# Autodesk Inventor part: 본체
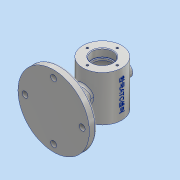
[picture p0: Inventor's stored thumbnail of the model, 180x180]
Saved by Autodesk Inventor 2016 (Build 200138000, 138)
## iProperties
Created: 2018-12
Part Number: 본체
Material: 알루미늄 6061
Document SubType Name: Modeling
Designer: 3sil_cad0123
Density: 2.7 g/cm^3
Appearance: 알루미늄 - 평지
Mass: 685.1 g
Surface Area: 555.675 cm^2
Volume: 253.741 cm^3
Author: 3sil_cad0123
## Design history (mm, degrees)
sketch "스케치2"
  geometry: C1 r 30 at (0, 0); C2 r 14 at (0, 0); C3 r 25 at (0, 0); 1 further point
  constraints: 3 centre point, 3 coincident
  dimensions: "d3" = 60 diameter of C1; "d4" = 28 diameter of C2; "d5" = 50 diameter of C3
extrude "돌출1" new body sketch "스케치2" stored distance "d6" = 70; taper "d7" = 0 deg
extrude "돌출2" cut sketch "스케치2" stored distance "d8" = 70; taper "d9" = 0 deg
extrude "돌출3" cut sketch "스케치2" stored distance "d10" = 40; taper "d11" = 0 deg
sketch "스케치3" dims "d13" = 46
  geometry: L1 (0, 0)-(0, 23); C1 r 14 at (0, 0) reference; C2 r 30 at (0, 0) reference; C3 r 16 at (0, 0); C4 r 1.692 at (0, 23)
  constraints: 3 coincident, 2 centre point, 2 end point, 1 vertical, 1 vertical alignment, 2 other
  dimensions: "d12" = 32 diameter of C3
extrude "돌출4" cut sketch "스케치3" distance "d14" = 12; taper "d15" = 0 deg
sketch "스케치4" dims "d16" = 46
  geometry: L1 (0, 23)-(0, 26.218); C1 r 30 at (0, 0) reference; 1 further point
  constraints: 2 end point, 1 coincident, 1 vertical, 1 vertical alignment, 2 other
hole "구멍1" sketch "스케치4" at (0, 23) diameter "d17" = 3.242; stored, may be unused: countersink angle "d21" = 90 deg, drill point angle "d23" = 118 deg; dims "d18" = 8, "d19" = 4, "d20" = 2, "d22" = 10
node "작업 평면1"
sketch "스케치5"
  geometry: L1 (0, -75)-(55, -75); L2 (55, -75)-(55, -64); L3 (0, -58.127)-(0, -75); L4 (0, -75)-(12, -75); L5 (12, -52.478)-(12, -26.195); L6 (12, -26.195)-(0, -26.195); L7 (0, -26.195)-(0, -75); L8 (55, -64)-(12, -52.478); L9 (0, 27.709)-(10, 27.709); L10 (10, 27.709)-(10, 37); L11 (10, 37)-(0, 37); L12 (0, 37)-(0, 27.709); 1 further point
  constraints: 24 end point, 5 parallel, 3 horizontal, 3 perpendicular
  dimensions: "d27" = 55 distance of L1.start L1.end; "d29" = 75 deg angle of L2 L8; "d30" = 12 distance between parallel lines of L5 L7; "d31" = 75 distance from line of point (0, 0) L1; "d32" = 11 distance of L1.end L2.end; "d33" = 10 distance of L10.end L11.end; "d34" = 112 distance between parallel lines of L11 L1
revolve "회전1" stored, may be unused: angle "d35" = 90 deg
revolve "회전2" stored, may be unused: angle "d36" = 90 deg
sketch "스케치6"
  geometry: C1 r 10 at (0, 0) reference; C2 r 5 at (0, 0)
  constraints: 1 centre point, 1 coincident
  dimensions: "d37" = 10 diameter of C2
extrude "돌출5" cut sketch "스케치6" distance "d38" = 27.5; taper "d39" = 0 deg
sketch "스케치7" dims "d41" = 88
  geometry: C1 r 5 at (0, 0) reference; C2 r 4.5 at (0, 44); 1 further point
  constraints: 1 centre point, 1 coincident, 1 vertical alignment, 2 other
  dimensions: "d40" = 9 diameter of C2
extrude "돌출6" cut sketch "스케치7" distance "d42" = 27.5; taper "d43" = 0 deg
node "작업 평면2"
sketch "스케치8"
  geometry: C1 r 7 at (0, 44); 3 further points
  constraints: 1 centre point, 1 coincident, 2 other
  dimensions: "d45" = 14 diameter of C1
extrude "돌출7" cut sketch "스케치8" distance "d46" = 27.5; taper "d47" = 0 deg
node "작업 평면3"
sketch "스케치9"
  geometry: L1 (3.495, 24.345)-(3.495, 10.268); L2 (3.495, 10.268)-(-40.465, 10.268); L3 (-40.465, 10.268)-(-40.465, 24.345); L4 (-40.465, 24.345)-(3.495, 24.345); 1 further point
  constraints: 2 other
extrude "돌출8" join sketch "스케치9" stored distance "d52" = 27.5; taper "d53" = 0 deg
fillet "모깎기1" dims "d54" = 3
fillet "모깎기2" dims "d55" = 0.3
chamfer "모따기1" distance "d56" = 1; stored, may be unused: second distance "d57" = 2, angle "d58" = 45 deg
node "솔리드1"
pattern_circular "원형 패턴1" dims angle "d25" = 360 deg
mirror "대칭1"
pattern_circular "원형 패턴2" dims angle "d49" = 360 deg
other parameters: "d51" = 30.5
